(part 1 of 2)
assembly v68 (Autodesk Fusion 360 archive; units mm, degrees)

design "assembly" references "rear_port_bumber", "camera_w_shroud", "Wemos Battery Shield V3", "M5StickC", "mounting_adapter_v2", "Raspberry PI Zero W", "Rover_C_chassis_plate"
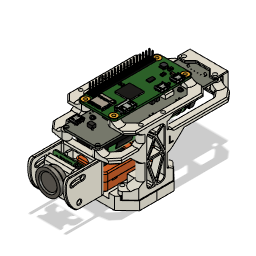
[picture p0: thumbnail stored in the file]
component_insert "Component Insert1"
component_insert "Component Insert2"
component_insert "Component Insert3"
component_insert "Component Insert4"
joint "Assemble1" alignAngle 180 alignOffsetX -5 alignOffsetY 0 alignOffsetZ 4
component_insert "Component Insert6"
joint "Assemble2" alignAngle 0 alignOffsetX 0 alignOffsetY 0 alignOffsetZ 0
joint "Assemble8" alignAngle -90 alignOffsetX 0 alignOffsetY 0 alignOffsetZ 0
position "Position1"
ground "Ground1"
position "Position2"
component_insert "Component Insert10"
joint "Assemble17" alignAngle -90 alignOffsetX 0 alignOffsetY 0 alignOffsetZ 0
joint "Assemble18" alignAngle 0 alignOffsetX 0 alignOffsetY 0 alignOffsetZ 0
component_insert "Component Insert11"
position "Position3"
joint "Assemble20" alignAngle 180 alignOffsetX 0 alignOffsetY 0 alignOffsetZ 0

design "Rover_C_chassis_plate"
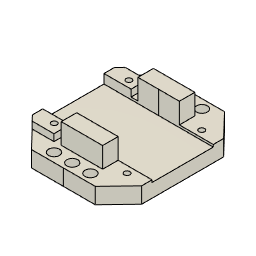
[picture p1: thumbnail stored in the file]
sketch "Sketch1" plane through (0, 0, 0) normal (0, 1, 0) x axis (1, 0, 0)
  line L1 (-14, 28.4) -> (0, 28.4)
  line L2 (-24, 18) -> (-14, 28.4)
  line L3 (-24, 0) -> (-24, 18)
  line L4 (-24, 0) -> (0, 0)
  line L5 (0, 28.4) -> (0, 0)
  line L6 (24, 18) -> (14, 28.4)
  line L7 (24, 0) -> (24, 18)
  line L8 (14, 28.4) -> (0, 28.4)
  line L9 (-24, -18) -> (-14, -28.4)
  line L10 (-14, -28.4) -> (0, -28.4)
  line L11 (14, -28.4) -> (0, -28.4)
  line L12 (24, -18) -> (14, -28.4)
  line L13 (24, 0) -> (24, -18)
  line L14 (-24, 0) -> (-24, -18)
  circle C1 centre (-8, 24.5) radius 2.4
  arc A1 centre (0, 24.5) radius 2.4 clockwise from (0, 22.1) to (0, 26.9)
  circle C2 centre (-16, 16.4) radius 1.25
  circle C3 centre (16, 16.4) radius 1.25
  circle C4 centre (8, 24.5) radius 2.4
  arc A2 centre (0, 24.5) radius 2.4 clockwise from (0, 26.9) to (0, 22.1)
  circle C5 centre (16, -16.4) radius 1.25
  circle C6 centre (8, -24.5) radius 2.4
  arc A3 centre (0, -24.5) radius 2.4 clockwise from (0, -22.1) to (0, -26.9)
  arc A4 centre (0, -24.5) radius 2.4 clockwise from (0, -26.9) to (0, -22.1)
  circle C7 centre (-8, -24.5) radius 2.4
  circle C8 centre (-16, -16.4) radius 1.25
  point P6 (-8, 24.5)
  point P7 (0, 24.5)
  point P1 (0, 0)
  point P11 (0, 0)
  point P12 (0, 0)
  point P8 (0, 22.1)
  point P9 (0, 26.9)
  point P13 (0, 26.9)
  point P2 (0, 28.4)
  point P22 (0, 28.4)
  point P3 (-14, 28.4)
  point P14 (14, 28.4)
  point P4 (-24, 18)
  point P15 (24, 18)
  point P5 (-24, 0)
  point P16 (24, 0)
  point P21 (0, 22.1)
  point P20 (0, 26.9)
  point P25 (0, -28.4)
  point P23 (-14, -28.4)
  point P24 (-24, -18)
  point P40 (-24, 0)
  point P37 (0, -22.1)
  point P36 (0, -26.9)
  point P27 (14, -28.4)
  point P28 (24, -18)
  point P29 (24, 0)
  point P34 (0, -26.9)
  point P33 (0, -22.1)
  point P26 (0, -28.4)
  point P10 (-16, 16.4)
  perpendicular L1 L3
  equal C1 A1
  horizontal P6 P7
  coincident P1 P11
  perpendicular L3 L4
  coincident P1 P12
  perpendicular L1 L5
  coincident P7 L5
  vertical L5
  coincident P8 L5
  coincident P9 L5
  coincident P9 P13
  symmetric P2 L5 P22
  symmetric P3 L5 P14
  symmetric P4 L5 P15
  symmetric P5 L5 P16
  symmetric C1 L5 C4
  symmetric P8 L5 P21
  symmetric P9 L5 P20
  symmetric A1 L5 A2
  symmetric C2 L5 C3
  symmetric P2 L4 P25
  symmetric P3 L4 P23
  symmetric P4 L4 P24
  symmetric P5 L4 P40
  symmetric C1 L4 C7
  symmetric P8 L4 P37
  symmetric P9 L4 P36
  symmetric A1 L4 A4
  symmetric C2 L4 C8
  symmetric L4 P14 P27
  symmetric L4 P15 P28
  symmetric L4 P16 P29
  symmetric L4 C3 C5
  symmetric L4 C4 C6
  symmetric L4 P20 P34
  symmetric L4 P21 P33
  symmetric L4 A2 A3
  symmetric L4 P22 P26
  dimension "d6" diameter C1 = 4.8
  dimension "d8" distance P6 P7 = 8
  dimension "d19" diameter C2 = 2.5
  dimension "d20" distance L3 P10 = 8
  dimension "d22" distance L1 P10 = 12
  dimension "d24" distance P2 P3 = 14
  dimension "d25" distance L3 L5 = 24
  dimension "d26" distance L1 L4 = 28.4
  dimension "d27" distance P4 P5 = 18
  dimension "d28" distance P2 P13 = 1.5
extrude "Extrude2" new body sketch "Sketch1" profile of L1 L2 L3 C1 A1 C2 L6 L7 C3 C4 A2 L8 L9 L10 L11 L12 L13 C5 C6 A3 A4 C7 C8 L14 along normal blind 7
sketch "Sketch2" plane through (0, 7, 0) normal (0, 1, 0) x axis (-1, 0, 0)
  line L1 (-14, 28.4) -> (0, 28.4)
  line L2 (-24, 18) -> (-14, 28.4)
  line L3 (-24, -18) -> (-24, 18)
  line L4 (-14, -28.4) -> (-24, -18)
  line L5 (0, -28.4) -> (-14, -28.4)
  line L6 (14, -28.4) -> (0, -28.4)
  line L7 (24, -18) -> (14, -28.4)
  line L8 (24, 18) -> (24, -18)
  line L9 (14, 28.4) -> (24, 18)
  line L10 (0, 28.4) -> (14, 28.4)
  line L11 (24, 0) -> (-24, 0)
  line L12 (0, -28.4) -> (0, 28.4)
  line L13 (-24, 13.45) -> (0, 13.45)
  line L14 (-9.1, 20.25) -> (-9.1, 13.45)
  line L15 (0, 20.25) -> (-9.1, 20.25)
  line L16 (9.1, 20.25) -> (9.1, 13.45)
  line L17 (0, 20.25) -> (9.1, 20.25)
  line L18 (24, 13.45) -> (0, 13.45)
  line L19 (0, -20.25) -> (-9.1, -20.25)
  line L20 (0, -20.25) -> (9.1, -20.25)
  line L21 (24, -13.45) -> (0, -13.45)
  line L22 (9.1, -20.25) -> (9.1, -13.45)
  line L23 (-9.1, -20.25) -> (-9.1, -13.45)
  line L24 (-24, -13.45) -> (0, -13.45)
  line L25 (12.1, 20.45) -> (12.1, 13.45)
  line L26 (21.6442, 20.45) -> (12.1, 20.45)
  line L27 (21.6442, -20.45) -> (12.1, -20.45)
  line L28 (12.1, -20.45) -> (12.1, -13.45)
  line L29 (-14, 28.4) -> (0, 28.4)
  line L30 (-24, 18) -> (-14, 28.4)
  line L31 (-24, -18) -> (-24, 18)
  line L32 (-14, -28.4) -> (-24, -18)
  line L33 (0, -28.4) -> (-14, -28.4)
  line L34 (14, -28.4) -> (0, -28.4)
  line L35 (24, -18) -> (14, -28.4)
  line L36 (24, 18) -> (24, -18)
  line L37 (14, 28.4) -> (24, 18)
  line L38 (0, 28.4) -> (14, 28.4)
  circle C1 centre (-8, 24.5) radius 2.4
  circle C2 centre (8, -24.5) radius 2.4
  circle C3 centre (-16, 16.4) radius 1.25
  circle C4 centre (0, -24.5) radius 2.4
  circle C5 centre (-8, -24.5) radius 2.4
  circle C6 centre (-16, -16.4) radius 1.25
  circle C7 centre (16, -16.4) radius 1.25
  circle C8 centre (0, 24.5) radius 2.4
  circle C9 centre (16, 16.4) radius 1.25
  circle C10 centre (8, 24.5) radius 2.4
  circle C11 centre (-16, 16.4) radius 1.25
  circle C12 centre (0, 24.5) radius 2.4
  circle C13 centre (8, -24.5) radius 2.4
  circle C14 centre (16, 16.4) radius 1.25
  circle C15 centre (-16, -16.4) radius 1.25
  circle C16 centre (0, -24.5) radius 2.4
  circle C17 centre (-8, 24.5) radius 2.4
  circle C18 centre (-8, -24.5) radius 2.4
  circle C19 centre (16, -16.4) radius 1.25
  circle C20 centre (8, 24.5) radius 2.4
  point P15 (-24, -18)
  point P23 (-24, 0)
  point P24 (24, 0)
  point P12 (0, 28.4)
  point P25 (0, 28.4)
  point P18 (0, -28.4)
  point P26 (0, -28.4)
  point P27 (0, 13.45)
  point P28 (-24, 13.45)
  point P29 (-9.1, 13.45)
  point P31 (0, 20.25)
  point P35 (0, 13.45)
  point P36 (24, 13.45)
  point P32 (9.1, 13.45)
  point P30 (-9.1, 20.25)
  point P33 (9.1, 20.25)
  point P34 (0, 20.25)
  point P45 (0, -13.45)
  point P46 (-24, -13.45)
  point P44 (-9.1, -13.45)
  point P37 (-9.1, -20.25)
  point P38 (0, -20.25)
  point P43 (9.1, -13.45)
  point P39 (9.1, -20.25)
  point P40 (0, -20.25)
  point P41 (0, -13.45)
  point P42 (24, -13.45)
  point P47 (12.1, 13.45)
  point P49 (21.6442, 20.45)
  point P52 (12.1, -13.45)
  point P48 (12.1, 20.45)
  point P50 (12.1, -20.45)
  point P51 (21.6442, -20.45)
  coincident P15 P23
  midpoint L8 P24
  coincident P12 P25
  coincident P18 P26
  coincident L12 P27
  coincident L3 P28
  perpendicular L3 L13
  coincident L13 P29
  perpendicular L13 L14
  coincident L12 P31
  perpendicular L12 L15
  symmetric L12 P27 P35
  symmetric L12 P28 P36
  symmetric L12 P29 P32
  symmetric L12 P30 P33
  symmetric L12 P31 P34
  symmetric L11 P27 P45
  symmetric L11 P28 P46
  symmetric L11 P29 P44
  symmetric L11 P30 P37
  symmetric L11 P31 P38
  symmetric L11 P32 P43
  symmetric L11 P33 P39
  symmetric L11 P34 P40
  symmetric L11 P35 P41
  symmetric L11 P36 P42
  coincident L18 P47
  perpendicular L18 L25
  coincident L9 P49
  perpendicular L25 L26
  symmetric L11 P47 P52
  symmetric L11 P48 P50
  symmetric L11 P49 P51
  dimension "d32" distance P29 P30 = 6.8
  dimension "d33" distance P30 P31 = 9.1
  dimension "d34" distance L11 L15 = 20.25
  dimension "d39" distance L16 L25 = 3
  dimension "d40" distance L18 L26 = 7
extrude "Extrude3" cut sketch "Sketch2" profile of L3 L8 L13 L18 L21 L24 against normal blind 1
extrude "Extrude4" add sketch "Sketch2" profile of C4 L13 L14 L15 L16 L17 L18 L19 L20 L21 L22 L23 L24 along normal blind 9
extrude "Extrude5" add sketch "Sketch2" profile of C7 C9 L7 L8 L9 L18 L21 L25 L26 L27 L28 along normal blind 3

design "Cam V2.1 v1"
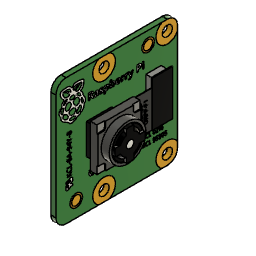
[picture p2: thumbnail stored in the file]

design "M5StickC"
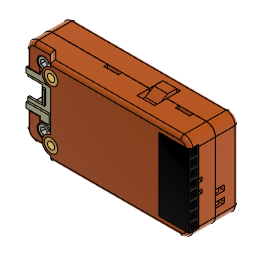
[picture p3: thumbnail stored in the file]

design "rear_port_bumber"
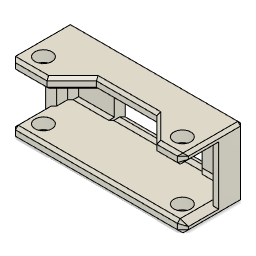
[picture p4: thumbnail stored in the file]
sketch "Sketch1" plane through (0, 0, 0) normal (0, 0, 1) x axis (1, 0, 0)
  line L1 (-5.75, 2.75) -> (8.25, 2.75)
  line L2 (-5.75, -3.75) -> (-5.75, 2.75)
  line L3 (8.25, -3.75) -> (-5.75, -3.75)
  line L4 (8.25, 2.75) -> (8.25, -3.75)
  line L5 (-15.75, 6.3) -> (15.75, 6.3)
  line L6 (-15.75, -6.3) -> (-15.75, 6.3)
  line L7 (15.75, -6.3) -> (-15.75, -6.3)
  line L8 (15.75, 6.3) -> (15.75, -6.3)
  line L9 (11.25, 4.3) -> (15.75, 4.3)
  line L10 (11.25, 6.3) -> (11.25, 4.3)
  line L11 (0, -6.3) -> (0, 6.3)
  line L12 (-11.25, 4.3) -> (-15.75, 4.3)
  line L13 (-11.25, 6.3) -> (-11.25, 4.3)
  line L14 (-15.75, 0) -> (15.75, 0)
  line L15 (11.25, -4.3) -> (15.75, -4.3)
  line L16 (11.25, -6.3) -> (11.25, -4.3)
  line L17 (-11.25, -6.3) -> (-11.25, -4.3)
  line L18 (-11.25, -4.3) -> (-15.75, -4.3)
  line L19 (1.25, -3.75) -> (1.25, 2.75)
  line L20 (-5.75, -0.5) -> (8.25, -0.5)
  line L21 (14.25, -4.3) -> (14.25, 4.3)
  line L22 (-14.25, -4.3) -> (-14.25, 4.3)
  point P10 (15.75, 4.3)
  point P12 (11.25, 6.3)
  point P13 (0, 6.3)
  point P14 (0, -6.3)
  point P15 (-15.75, 4.3)
  point P11 (11.25, 4.3)
  point P16 (-11.25, 4.3)
  point P17 (-11.25, 6.3)
  point P18 (15.75, 0)
  point P19 (-15.75, 0)
  point P20 (15.75, -4.3)
  point P21 (11.25, -4.3)
  point P22 (11.25, -6.3)
  point P25 (-15.75, -4.3)
  point P23 (-11.25, -4.3)
  point P24 (-11.25, -6.3)
  point P1 (0, 0)
  point P26 (1.25, 2.75)
  point P27 (1.25, -3.75)
  point P28 (8.25, -0.5)
  point P29 (-5.75, -0.5)
  point P30 (14.25, 4.3)
  point P31 (14.25, -4.3)
  point P32 (-14.25, 4.3)
  point P33 (-14.25, -4.3)
  point P2 (8.25, 2.75)
  point P3 (-5.75, 2.75)
  point P5 (8.25, -3.75)
  horizontal L1
  vertical L2
  horizontal L3
  vertical L4
  horizontal L5
  vertical L6
  horizontal L7
  vertical L8
  coincident L8 P10
  perpendicular L8 L9
  coincident L5 P12
  perpendicular L9 L10
  midpoint L5 P13
  midpoint L7 P14
  symmetric P10 L11 P15
  symmetric P11 L11 P16
  symmetric P12 L11 P17
  midpoint L8 P18
  coincident L6 P19
  perpendicular L6 L14
  symmetric P10 L14 P20
  symmetric P11 L14 P21
  symmetric P12 L14 P22
  symmetric P15 L14 P25
  symmetric P16 L14 P23
  symmetric P17 L14 P24
  midpoint P1 L11
  midpoint L1 P26
  midpoint L3 P27
  midpoint L4 P28
  midpoint L2 P29
  coincident L9 P30
  coincident L15 P31
  perpendicular L15 L21
  symmetric L11 P30 P32
  symmetric L11 P31 P33
  dimension "d1" distance P2 P3 = 14
  dimension "d11" distance P2 P5 = 6.5
  dimension "d18" distance P11 P12 = 2
  dimension "d19" distance P10 P11 = 4.5
  dimension "d29" distance L7 L14 = 6.3
  dimension "d30" distance P1 L8 = 15.75
  dimension "d33" distance L11 L19 = 1.25
  dimension "d34" distance L14 L20 = 0.5
  dimension "d57" distance L8 L21 = 1.5
extrude "Extrude1" new body sketch "Sketch1" profile of L1 L2 L3 L4 L5 L6 L7 L8 along normal blind 1.5
extrude "Extrude2" sketch "Sketch1" profile of L5 L6 L7 L8 L9 L10 L12 L13 L15 L16 L17 L18 blind 10
extrude "Extrude4" add of existing geometry to an object
extrude "Extrude5" add of existing geometry to an object
extrude "Extrude8" sketch "Sketch1" profile of L6 L8 L9 L12 L15 L18 L21 L22 blind 4
sketch "Sketch4" plane through (0, 6.3, 0) normal (0, 1, 0) x axis (-1, 0, 0)
  line L1 (15.75, 0) -> (-15.75, 0)
  line L2 (15.75, 11.5) -> (15.75, 0)
  line L3 (-15.75, 11.5) -> (15.75, 11.5)
  line L4 (-15.75, 0) -> (-15.75, 11.5)
  line L5 (-8.75, 7) -> (-8.75, 11.5)
  line L6 (6.75, 7) -> (-8.75, 7)
  line L7 (6.75, 11.5) -> (6.75, 7)
  point P6 (-8.75, 11.5)
  point P9 (6.75, 11.5)
  point P7 (-8.75, 7)
  point P8 (6.75, 7)
  coincident L3 P6
  perpendicular L3 L5
  perpendicular L5 L6
  coincident L3 P9
  perpendicular L3 L7
  dimension "d39" distance P7 P8 = 15.5
  dimension "d40" distance P6 P7 = 4.5
  dimension "d41" distance L4 L5 = 7
extrude "Extrude6" cut sketch "Sketch4" profile of L3 L5 L6 L7 to an object
chamfer "Chamfer1" distance 1 distance 2.25 distance 1 distance 0.5
sketch "Sketch5" plane through (0, 6.3, 0) normal (0, 1, 0) x axis (-1, 0, 0)
  line L1 (-6.5, 7) -> (4.5, 7)
  line L2 (-15.25, 11) -> (-10.5, 11)
  line L3 (-15.25, 1) -> (-15.25, 11)
  line L4 (15.25, 1) -> (-15.25, 1)
  line L5 (15.25, 11) -> (15.25, 1)
  line L6 (0, 11) -> (0, 0)
  line L7 (-15.75, 1) -> (-15.75, 10.5)
  line L8 (-10.5, 11) -> (-6.5, 7)
  line L9 (8.5, 11) -> (15.25, 11)
  line L10 (4.5, 7) -> (8.5, 11)
  line L11 (-14.75, 11.5) -> (-11, 11.5)
  line L12 (9, 11.5) -> (14.75, 11.5)
  circle C1 centre (-12.65, 8.5) radius 1.55
  circle C2 centre (12.65, 8.5) radius 1.55
  point P1 (0, 0)
  point P10 (0, 0)
  point P4 (-10.5, 11)
  point P11 (0, 11)
  point P9 (-12.65, 8.5)
  coincident P1 P10
  perpendicular L4 L6
  horizontal P4 P11
  symmetric C1 L6 C2
  dimension "d50" diameter C1 = 3.1
  dimension "d56" distance P9 L6 = 12.65 (= "( 25.3 / 2 ) * 1 mm")
extrude "Extrude7" cut sketch "Sketch5" profile of C1 C2 to an object
chamfer "Chamfer2" distance 0.5
sketch "Sketch6" plane through (0, 0, 0) normal (0, 0, -1) x axis (-1, 0, 0)
  line L1 (-14.75, -5.3) -> (-14.75, 5.3)
  line L2 (14.75, -5.3) -> (-14.75, -5.3)
  line L3 (14.75, 5.3) -> (14.75, -5.3)
  line L4 (-14.75, 5.3) -> (14.75, 5.3)
  line L5 (-8.75, 3.25) -> (-8.75, -4.25)
  line L6 (6.25, 3.25) -> (-8.75, 3.25)
  line L7 (6.25, -4.25) -> (6.25, 3.25)
  line L8 (-8.75, -4.25) -> (6.25, -4.25)
  curve K1
  curve K2
  curve K3
  curve K4
  coincident L7
  coincident L4
  coincident L3
  vertical K2
  coincident L2
  dimension "d62" Text1-Height = 4.8
extrude "Extrude9" cut sketch "Sketch6" against normal blind 0.5
named bodies: "bumper"

design "adjustable_camera_shroud_mount_w_lens"
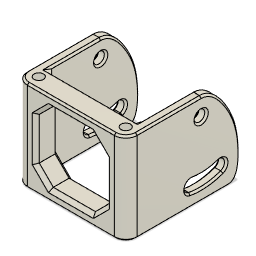
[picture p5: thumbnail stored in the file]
sketch "Sketch1" plane through (0, 0, 0) normal (0, 1, 0) x axis (1, 0, 0)
  line L1 (0, 3.25) -> (0, -3.25)
  line L2 (12.4, 0) -> (-12.4, 0)
  line L3 (12.4, 3.25) -> (-12.4, 3.25)
  line L4 (12.4, -3.25) -> (-12.4, -3.25)
  line L5 (-8.15, -3.25) -> (-8.15, 3.25)
  line L6 (8.15, -3.25) -> (8.15, 3.25)
  line L7 (-15.65, 40) -> (-15.65, 0)
  line L8 (-13, 40) -> (-15.65, 40)
  line L9 (15.65, 40) -> (15.65, 0)
  line L10 (13, 40) -> (15.65, 40)
  line L11 (-15.65, 3.25) -> (-12.4, 3.25)
  line L12 (15.65, 3.25) -> (12.4, 3.25)
  line L13 (-13, 3.25) -> (-13, 40)
  line L14 (13, 3.25) -> (13, 40)
  circle C1 centre (-12.4, 0) radius 1.35
  circle C2 centre (12.4, 0) radius 1.35
  arc A1 centre (-12.4, 0) radius 3.25 clockwise from (-12.4, -3.25) to (-12.4, 3.25)
  arc A2 centre (12.4, 0) radius 3.25 clockwise from (12.4, 3.25) to (12.4, -3.25)
  arc A3 centre (-12.4, 0) radius 3.25 clockwise from (-12.4, 3.25) to (-12.4, -3.25)
  point P1 (0, 0)
  point P2 (-12.4, 0)
  point P5 (12.4, 0)
  point P6 (-12.4, 0)
  point P7 (12.4, 0)
  point P8 (0, 0)
  point P9 (-12.4, 3.25)
  point P11 (-12.4, -3.25)
  point P12 (12.4, -3.25)
  point P10 (12.4, 3.25)
  point P13 (-12.4, 0)
  point P4 (0, 3.25)
  point P15 (-11.05, 0)
  point P16 (-15.65, 0)
  point P17 (-13.75, 0)
  point P19 (-9.15, 0)
  point P20 (-8.15, 3.25)
  point P21 (-8.15, -3.25)
  point P22 (8.15, 3.25)
  point P23 (8.15, -3.25)
  point P24 (-15.65, 0)
  point P27 (15.65, 0)
  point P25 (-15.65, 40)
  point P28 (15.65, 40)
  point P26 (-13, 40)
  point P29 (13, 40)
  point P30 (-15.65, 3.25)
  point P31 (15.65, 3.25)
  point P32 (-13, 3.25)
  point P33 (13, 3.25)
  vertical L1
  midpoint P1 L1
  horizontal P2 P5
  equal C1 C2
  coincident P2 P6
  coincident P5 P7
  midpoint L2 P8
  coincident P1 P8
  perpendicular L1 L3
  vertical P2 P9
  vertical P2 P11
  vertical P5 P12
  vertical P5 P10
  tangent L3 A1
  tangent L3 A2
  coincident P2 P13
  coincident P4 L3
  coincident L2 P15
  coincident C1 P15
  midpoint A1 P16
  coincident C1 P17
  tangent L4 A3
  midpoint A3 P19
  coincident L3 P20
  coincident L4 P21
  perpendicular L4 L5
  symmetric L1 P20 P22
  symmetric L1 P21 P23
  coincident P16 P24
  tangent A1 L7
  vertical L7
  perpendicular L7 L8
  symmetric L1 P24 P27
  symmetric L1 P25 P28
  symmetric L1 P26 P29
  coincident L7 P30
  tangent A1 L11
  coincident L9 P31
  tangent A2 L12
  coincident L3 P32
  perpendicular L3 L13
  coincident L3 P33
  perpendicular L3 L14
  dimension "d2" diameter C1 = 2.7
  dimension "d3" distance P2 P5 = 24.8 (= "25.3 mm - 0.5 mm")
  dimension "d4" distance L3 L4 = 6.5
  dimension "d15" distance P19 L5 = 1
  dimension "d19" distance P16 L8 = 40
  dimension "d24" distance L13 L14 = 26
extrude "Extrude1" new body sketch "Sketch1" profile of C1 C2 L3 L4 A1 A2 A3 L5 L6 along normal blind 26
extrude "Extrude3" cut sketch "Sketch1" profile of C1 C2 along normal blind 6
extrude "Extrude4" add sketch "Sketch1" profile of L3 L4 L5 L6 against normal blind 4
extrude "Extrude5" add sketch "Sketch1" profile of A1 A2 L7 L8 L9 L10 L11 L12 L13 L14 to an object
extrude "Extrude8" sketch "Sketch1" profile of C1 C2 blind -6
sketch "Sketch2" plane through (15.65, 0, 0) normal (1, 0, 0) x axis (0, 0, -1)
  line L1 (0, 26) -> (40, 26)
  line L2 (0, 0) -> (0, 26)
  line L3 (40, 0) -> (0, 0)
  line L4 (40, 26) -> (40, 0)
  line L5 (18.25, 21) -> (18.25, 5)
  line L6 (3.25, 26) -> (3.25, 0)
  line L7 (3.25, 13) -> (40, 13)
  line L8 (18.25, 21) -> (24.3038, 4.3674)
  line L9 (18.25, 21) -> (15.1764, 3.5689)
  line L10 (25.8934, 0) -> (24.3038, 4.3674)
  curve K1 (18.25, 26) -> (25.8934, 0)
  curve K2 (28.3934, 0) -> (23.3934, 0)
  curve K3 (15.75, 26) -> (20.75, 26)
  circle C1 centre (18.25, 21) radius 1.55
  circle C2 centre (18.25, 5) radius 1.55
  arc A1 centre (18.25, 21) radius 17.7 clockwise from (24.3038, 4.3674) to (15.1764, 3.5689)
  arc A2 centre (18.25, 21) radius 14.3 clockwise from (23.1409, 7.5624) to (15.7668, 6.9172)
  arc A3 centre (23.7223, 5.9649) radius 1.7 clockwise from (23.1409, 7.5624) to (24.3038, 4.3674)
  arc A4 centre (15.4716, 5.2431) radius 1.7 clockwise from (15.1764, 3.5689) to (15.7668, 6.9172)
  point P7 (18.25, 21)
  point P8 (18.25, 21)
  point P6 (18.25, 5)
  point P9 (18.25, 5)
  point P10 (3.25, 0)
  point P11 (3.25, 26)
  point P14 (18.25, 13)
  point P15 (18.25, 21)
  point P18 (18.25, 21)
  point P19 (18.25, 21)
  point P21 (15.7668, 6.9172)
  point P20 (18.25, 21)
  point P22 (23.1409, 7.5624)
  point P25 (25.8934, 0)
  point P13 (3.25, 13)
  point P12 (40, 13)
  point P28 (18.25, 26)
  point P30 (28.3934, 0)
  point P31 (20.75, 26)
  point P1 (0, 0)
  point P16 (15.1764, 3.5689)
  point P26 (29.25, 8)
  point P27 (26.25, 19)
  point P32 (15.75, 26)
  vertical L5
  coincident P7 P8
  coincident P6 P9
  equal C1 C2
  coincident L3 P10
  coincident L1 P11
  perpendicular L1 L6
  midpoint L5 P14
  coincident L7 P14
  coincident P7 P15
  coincident P8 P18
  coincident P15 P19
  coincident L9 P21
  coincident P8 P20
  coincident L8 P22
  tangent A2 A3
  tangent A1 A4
  coincident L3 P25
  coincident L3 P25
  parallel L8 L10
  horizontal L7
  coincident L6 P13
  coincident L4 P12
  coincident L3 P25
  coincident L1 P28
  midpoint P25 K2
  coincident L3 P30
  midpoint P28 K3
  coincident L1 P31
  vertical P15 P28
  equal K2 K3
  dimension "d25" diameter C1 = 3.1
  dimension "d26" distance P6 P7 = 16
  dimension "d27" distance P1 L6 = 3.25
  dimension "d28" distance L5 L6 = 15
  dimension "d30" angle L8 L9 = 30
  dimension "d31" angle L5 L9 = 10
  dimension "d32" distance P16 P21 = 3.4
  dimension "d33" distance P15 P21 = 14.3
  dimension "d72" distance L3 L7 = 13
  dimension "d81" distance L7 P26 = 5
  dimension "d82" distance L7 P27 = 6
  dimension "d83" distance P26 P27 = 3
  dimension "d84" distance L5 P27 = 8
  dimension "d85" distance P31 P32 = 5
extrude "Extrude6" cut sketch "Sketch2" profile of L1 L3 L4 C1 A1 A2 A3 A4 to an object
sketch "Sketch3" plane through (0, 0, -3.25) normal (0, 0, -1) x axis (-1, 0, 0)
  line L1 (13, 0) -> (-13, 0)
  line L2 (13, 26) -> (13, 0)
  line L3 (-13, 26) -> (13, 26)
  line L4 (-13, 0) -> (-13, 26)
  line L5 (0, 26) -> (0, 0)
  line L6 (-10, 3) -> (10, 3)
  line L7 (-10, 23) -> (-10, 3)
  line L8 (10, 23) -> (-10, 23)
  line L9 (10, 3) -> (10, 23)
  line L10 (-10, 13) -> (10, 13)
  point P1 (0, 0)
  point P6 (0, 0)
  point P7 (0, 26)
  point P12 (0, 3)
  point P13 (0, 23)
  point P14 (-10, 13)
  point P15 (10, 13)
  point P16 (10, 13)
  point P17 (-10, 13)
  coincident P1 P6
  midpoint L3 P7
  horizontal L6
  vertical L7
  horizontal L8
  vertical L9
  midpoint L6 P12
  midpoint L8 P13
  midpoint L7 P14
  midpoint L9 P15
  coincident P15 P16
  coincident P14 P17
  midpoint L5 L10
  dimension "d45" distance P12 P13 = 20
  dimension "d46" distance P14 P15 = 20
extrude "Extrude7" cut sketch "Sketch3" profile of L6 L7 L8 L9 to an object
chamfer "Chamfer1" distance 4 distance 1 distance 0.5
chamfer "Chamfer2" distance 1
named bodies: "cam_bracket"

design "camera_w_shroud" references "macro_0.67xwideangle_lens", "lens_mount_adapter_maglock", "Cam V2.1 v1", "adjustable_camera_shroud_mount_w_lens", "camera_mounting_shroud", "fisheye_lens_180degFoV"
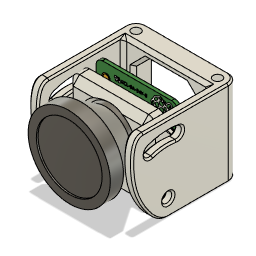
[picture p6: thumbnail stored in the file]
component_insert "Component Insert1"
component_insert "Component Insert2"
joint "Assemble1" alignAngle 180 alignOffsetX 0 alignOffsetY 0 alignOffsetZ 0
component_insert "Component Insert4"
component_insert "Component Insert5"
joint "Assemble2" alignAngle 180 alignOffsetX 0 alignOffsetY 0 alignOffsetZ 0
joint "Assemble3" alignAngle 0 alignOffsetX 0 alignOffsetY 0 alignOffsetZ 0
component_insert "Component Insert6"
joint "Assemble4" alignAngle 0 alignOffsetX 0 alignOffsetY 0 alignOffsetZ 0.5 RotateMinimum -20 RotateMaximum 10
position "Position1"
ground "Ground1"
component_insert "Component Insert7"
joint "Assemble5" alignAngle 0 alignOffsetX 0 alignOffsetY 0 alignOffsetZ 0

design "mounting_adapter_v2"
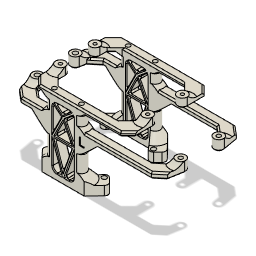
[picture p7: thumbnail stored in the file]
sketch "Sketch1" plane through (0, 0, 0) normal (0, 1, 0) x axis (1, 0, 0)
  line L1 (0, 28.4) -> (0, 0)
  line L2 (14, 28.4) -> (0, 28.4)
  line L3 (-14, 28.4) -> (0, 28.4)
  line L4 (-14, -28.4) -> (0, -28.4)
  line L5 (-24, 0) -> (-24, 18)
  line L6 (14, -28.4) -> (0, -28.4)
  line L7 (24, 18) -> (14, 28.4)
  line L8 (-24, -18) -> (-14, -28.4)
  line L9 (24, 0) -> (24, -18)
  line L10 (24, -18) -> (14, -28.4)
  line L11 (24, 0) -> (24, 18)
  line L12 (-24, 0) -> (-24, -18)
  line L13 (-24, 0) -> (0, 0)
  line L14 (-24, 18) -> (-14, 28.4)
  line L15 (24, 13.45) -> (-24, 13.45)
  line L16 (-9.1, 20.25) -> (-9.1, 13.45)
  line L17 (9.1, 20.25) -> (-9.1, 20.25)
  line L18 (9.1, 13.45) -> (9.1, 20.25)
  line L19 (24, -13.45) -> (-24, -13.45)
  line L20 (-9.1, -20.25) -> (-9.1, -13.45)
  line L21 (9.1, -20.25) -> (-9.1, -20.25)
  line L22 (9.1, -13.45) -> (9.1, -20.25)
  line L23 (-16, 28.4) -> (-16, 13.9)
  line L24 (0, 21.25) -> (-9, 21.25)
  line L25 (-9, 21.25) -> (-14.0357, 14.8536)
  line L26 (-20.5438, 17.4082) -> (-17.7678, 14.6322)
  line L27 (-14, 27.75) -> (-20.5781, 20.9088)
  line L28 (0, 27.75) -> (-14, 27.75)
  line L29 (22.4208, -18.9924) -> (18.4142, -14.9858)
  line L30 (9.3216, -21.25) -> (15.5858, -14.9858)
  line L31 (14, -27.75) -> (22.4208, -18.9924)
  line L32 (0, -27.75) -> (14, -27.75)
  line L33 (0, -21.25) -> (9.3216, -21.25)
  line L34 (0, -21.25) -> (-9, -21.25)
  line L35 (0, -27.75) -> (-14, -27.75)
  line L36 (-14, -27.75) -> (-22.2893, -19.1295)
  line L37 (-9, -21.25) -> (-14.0357, -14.8536)
  line L38 (-22.2893, -19.1295) -> (-17.7678, -14.6322)
  line L39 (0, 21.25) -> (9, 21.25)
  line L40 (9, 21.25) -> (14.0357, 14.8536)
  line L41 (20.5438, 17.4082) -> (17.7678, 14.6322)
  line L42 (14, 27.75) -> (20.5781, 20.9088)
  line L43 (0, 27.75) -> (14, 27.75)
  line L44 (-9.5511, 20.55) -> (-20.9231, 20.55)
  arc A1 centre (0, 24.5) radius 2.4 clockwise from (0, 22.1) to (0, 26.9)
  circle C1 centre (8, 24.5) radius 2.4
  circle C2 centre (16, -16.4) radius 1.55
  arc A2 centre (0, 24.5) radius 2.4 clockwise from (0, 26.9) to (0, 22.1)
  circle C3 centre (-16, 16.4) radius 1.55
  circle C4 centre (8, -24.5) radius 2.4
  circle C5 centre (-8, -24.5) radius 2.4
  arc A3 centre (0, -24.5) radius 2.4 clockwise from (0, -22.1) to (0, -26.9)
  circle C6 centre (-16, -16.4) radius 1.55
  circle C7 centre (-8, 24.5) radius 2.4
  arc A4 centre (0, -24.5) radius 2.4 clockwise from (0, -26.9) to (0, -22.1)
  circle C8 centre (16, 16.4) radius 1.55
  circle C9 centre (-16, 16.4) radius 2.5
  circle C10 centre (17, -16.4) radius 2
  circle C11 centre (-16, -16.4) radius 2.5
  arc A5 centre (-18.776, 19.176) radius 2.5 clockwise from (-20.5438, 17.4082) to (-20.5781, 20.9088)
  circle C12 centre (16, 16.4) radius 2.5
  arc A6 centre (18.776, 19.176) radius 2.5 clockwise from (20.5781, 20.9088) to (20.5438, 17.4082)
  arc A7 centre (-9, 24.5) radius 3.25 clockwise from (-9, 21.25) to (-9, 27.75)
  arc A8 centre (9, 24.5) radius 3.25 clockwise from (9, 27.75) to (9, 21.25)
  point P9 (0, 24.5)
  point P30 (-8, 24.5)
  point P16 (0, 0)
  point P26 (0, 0)
  point P27 (0, 0)
  point P37 (0, 22.1)
  point P13 (0, 26.9)
  point P28 (0, 26.9)
  point P18 (0, 28.4)
  point P39 (0, 28.4)
  point P2 (14, 28.4)
  point P22 (-14, 28.4)
  point P23 (24, 18)
  point P41 (-24, 18)
  point P10 (24, 0)
  point P17 (-24, 0)
  point P32 (0, 22.1)
  point P34 (0, 26.9)
  point P40 (0, -28.4)
  point P15 (-14, -28.4)
  point P25 (-24, -18)
  point P6 (-24, 0)
  point P7 (0, -22.1)
  point P3 (0, -26.9)
  point P31 (14, -28.4)
  point P24 (24, -18)
  point P19 (24, 0)
  point P11 (0, -26.9)
  point P14 (0, -22.1)
  point P29 (0, -28.4)
  point P1 (0, 0)
  point P42 (-24, 13.45)
  point P43 (24, 13.45)
  point P44 (-9.1, 13.45)
  point P47 (9.1, 13.45)
  point P48 (0, 20.25)
  point P49 (-24, -13.45)
  point P50 (24, -13.45)
  point P51 (-9.1, -13.45)
  point P45 (-9.1, 20.25)
  point P52 (-9.1, -20.25)
  point P46 (9.1, 20.25)
  point P53 (9.1, -20.25)
  point P54 (9.1, -13.45)
  point P56 (-16, 28.4)
  point P8 (-16, 16.4)
  point P58 (0, 21.25)
  point P55 (-16, 13.9)
  point P60 (-14.0357, 14.8536)
  point P61 (-17.7678, 14.6322)
  point P63 (0, 27.75)
  point P62 (-14, 27.75)
  point P57 (-9, 21.25)
  point P72 (-9, -21.25)
  point P73 (0, -21.25)
  point P77 (-14.0357, -14.8536)
  point P79 (-17.7678, -14.6322)
  point P74 (-14, -27.75)
  point P75 (0, -27.75)
  point P83 (9, 21.25)
  point P84 (0, 21.25)
  point P85 (14.0357, 14.8536)
  point P87 (17.7678, 14.6322)
  point P91 (14, 27.75)
  point P92 (0, 27.75)
  point P80 (-20.5438, 17.4082)
  point P88 (20.5438, 17.4082)
  point P81 (-20.5781, 20.9088)
  point P90 (20.5781, 20.9088)
  point P93 (-9, 27.75)
  point P94 (-9, 24.5)
  point P97 (9, 21.25)
  point P96 (9, 27.75)
  point P98 (-20.9231, 20.55)
  point P99 (-9.5511, 20.55)
  perpendicular L3 L5
  equal A1 C7
  horizontal P9 P30
  coincident P16 P26
  perpendicular L5 L13
  coincident P16 P27
  perpendicular L1 L3
  coincident P9 L1
  vertical L1
  coincident P37 L1
  coincident P13 L1
  coincident P13 P28
  symmetric P18 P39 L1
  symmetric P2 P22 L1
  symmetric P23 P41 L1
  symmetric P10 P17 L1
  symmetric L1 C1 C7
  symmetric P32 P37 L1
  symmetric P13 P34 L1
  symmetric L1 A1 A2
  symmetric L1 C3 C8
  symmetric P18 P40 L13
  symmetric P15 P22 L13
  symmetric P25 P41 L13
  symmetric P6 P17 L13
  symmetric C5 C7 L13
  symmetric P7 P37 L13
  symmetric P3 P13 L13
  symmetric A1 A4 L13
  symmetric C3 C6 L13
  symmetric P2 P31 L13
  symmetric P23 P24 L13
  symmetric P10 P19 L13
  symmetric C2 C8 L13
  symmetric C1 C4 L13
  symmetric P11 P34 L13
  symmetric P14 P32 L13
  symmetric A2 A3 L13
  symmetric P29 P39 L13
  coincident P1 P16
  coincident L5 P42
  coincident L11 P43
  perpendicular L11 L15
  coincident L15 P44
  perpendicular L15 L16
  perpendicular L16 L17
  coincident L15 P47
  perpendicular L15 L18
  coincident L1 P48
  midpoint L17 P48
  symmetric L13 P42 P49
  symmetric L13 P43 P50
  symmetric L13 P44 P51
  symmetric L13 P45 P52
  symmetric L13 P46 P53
  symmetric L13 P47 P54
  horizontal P22 P56
  coincident P8 L23
  coincident L1 P58
  perpendicular L1 L24
  concentric C3 C9
  coincident P55 C9
  coincident C9 P60
  vertical L23
  coincident C9 P61
  tangent C9 L26
  coincident L1 P63
  perpendicular L1 L28
  tangent C9 L25
  parallel L14 L27
  vertical P22 P62
  symmetric L13 P57 P72
  symmetric L13 P58 P73
  symmetric L13 C9 C11
  symmetric L13 P60 P77
  symmetric L13 P61 P79
  symmetric L13 P62 P74
  symmetric L13 P63 P75
  tangent L26 A5
  tangent L27 A5
  symmetric L1 P57 P83
  symmetric L1 P58 P84
  symmetric L1 C9 C12
  symmetric L1 P60 P85
  symmetric L1 P61 P87
  symmetric L1 P62 P91
  symmetric L1 P63 P92
  symmetric L1 P80 P88
  symmetric L1 P81 P90
  symmetric L1 A5 A6
  coincident L28 P93
  vertical P57 P94
  vertical P93 P94
  symmetric L1 P57 P97
  symmetric L1 P93 P96
  symmetric L1 A7 A8
  coincident L27 P98
  coincident L25 P99
  horizontal L44
  dimension "d6" diameter C7 = 4.8
  dimension "d8" distance P9 P30 = 8
  dimension "d19" diameter C3 = 3.1
  dimension "d20" distance P8 L5 = 8
  dimension "d22" distance P8 L3 = 12
  dimension "d24" distance P18 P22 = 14
  dimension "d25" distance L1 L5 = 24
  dimension "d26" distance L3 L13 = 28.4
  dimension "d27" distance P17 P41 = 18
  dimension "d28" distance P18 P28 = 1.5
  dimension "d13" distance P45 P46 = 18.2 (= "( 9.1 * 2 ) * 1 mm")
  dimension "d14" distance L15 L17 = 6.8
  dimension "d16" distance L13 P48 = 20.25
  dimension "d32" distance P48 L24 = 1
  dimension "d33" diameter C9 = 5
  dimension "d36" distance P34 P63 = 0.85
  dimension "d37" angle L23 L26 = 45
  dimension "d41" radius A5 = 2.5
  dimension "d51" distance P57 P58 = 9
  dimension "d102" distance L15 L44 = 7.1
extrude "Extrude1" new body sketch "Sketch1" profile of C3 C8 L24 C9 L25 L26 L27 L28 A5 L39 L40 C12 L41 A6 L42 L43 along normal blind 6
extrude "Extrude2" sketch "Sketch1" profile of A1 C1 A2 C7 L24 L28 L39 L43 A7 A8 blind 43
extrude "Extrude3" cut sketch "Sketch1" profile of C3 C9 L25 L26 L27 A5 L44 along normal blind 3
sketch "Sketch5" plane through (0, 49, 0) normal (0, 1, 0) x axis (-1, 0, 0)
  line L1 (9, -27.75) -> (-9, -27.75)
  line L2 (-9, -21.25) -> (9, -21.25)
  line L3 (-63.05, -14.65) -> (32.25, -14.65)
  line L4 (-65.05, 12.65) -> (-65.05, -12.65)
  line L5 (32.25, 14.65) -> (-63.05, 14.65)
  line L6 (34.25, -12.65) -> (34.25, 12.65)
  line L7 (-15.4, 14.65) -> (-15.4, -14.65)
  line L8 (-65.05, 0) -> (34.25, 0)
  line L9 (27.4335, -21.25) -> (9, -21.25)
  line L10 (29.0494, -12.0856) -> (27.4335, -21.25)
  line L11 (32.8876, -27.75) -> (9, -27.75)
  line L12 (35.4506, -13.2144) -> (32.8876, -27.75)
  line L13 (-58.2335, -21.25) -> (-9, -21.25)
  line L14 (-59.8494, -12.0856) -> (-58.2335, -21.25)
  line L15 (-63.6876, -27.75) -> (-9, -27.75)
  line L16 (-66.2506, -13.2144) -> (-63.6876, -27.75)
  line L17 (34.3, -12.65) -> (34.3, -10.1281)
  line L18 (-65.1, -10.1281) -> (-65.1, -12.65)
  line L19 (28.5884, -14.7) -> (32.25, -14.7)
  line L20 (-63.05, -14.7) -> (-59.3884, -14.7)
  arc A1 centre (9, -24.5) radius 3.25 clockwise from (9, -21.25) to (9, -27.75)
  arc A2 centre (-9, -24.5) radius 3.25 clockwise from (-9, -27.75) to (-9, -21.25)
  circle C1 centre (32.25, -12.65) radius 1.55
  circle C2 centre (-63.05, -12.65) radius 1.35
  circle C3 centre (32.25, -12.65) radius 3.25
  circle C4 centre (-63.05, -12.65) radius 3.25
  circle C5 centre (32.25, -12.65) radius 1.5
  arc A3 centre (32.25, -12.65) radius 2 clockwise from (34.25, -12.65) to (32.25, -14.65)
  arc A4 centre (32.25, 12.65) radius 2 clockwise from (32.25, 14.65) to (34.25, 12.65)
  arc A5 centre (-63.05, -12.65) radius 2 clockwise from (-63.05, -14.65) to (-65.05, -12.65)
  arc A6 centre (-63.05, 12.65) radius 2 clockwise from (-65.05, 12.65) to (-63.05, 14.65)
  circle C6 centre (32.25, 12.65) radius 1.5
  circle C7 centre (-63.05, -12.65) radius 1.5
  circle C8 centre (-63.05, 12.65) radius 1.5
  arc A7 centre (32.25, -12.65) radius 2.05 clockwise from (34.3, -12.65) to (32.25, -14.7)
  arc A8 centre (-63.05, -12.65) radius 2.05 clockwise from (-63.05, -14.7) to (-65.1, -12.65)
  point P8 (32.25, -12.65)
  point P9 (-63.05, -12.65)
  point P10 (12.25, -24.5)
  point P11 (-12.25, -24.5)
  point P15 (-15.4, -14.65)
  point P14 (32.25, -12.65)
  point P19 (32.25, -12.65)
  point P16 (-15.4, 14.65)
  point P29 (34.25, 0)
  point P30 (-65.05, 0)
  point P12 (32.25, -12.65)
  point P13 (-63.05, -12.65)
  point P25 (-63.05, -12.65)
  point P4 (9, -21.25)
  point P34 (9, -21.25)
  point P36 (29.0494, -12.0856)
  point P3 (9, -27.75)
  point P37 (9, -27.75)
  point P39 (35.4506, -13.2144)
  point P6 (-9, -21.25)
  point P40 (-9, -21.25)
  point P42 (-59.8494, -12.0856)
  point P2 (-9, -27.75)
  point P43 (-9, -27.75)
  point P45 (-66.2506, -13.2144)
  point P52 (34.3, -10.1281)
  point P53 (28.5884, -14.7)
  point P54 (-59.3884, -14.7)
  point P55 (-65.1, -10.1281)
  horizontal P8 P9
  midpoint A1 P10
  midpoint A2 P11
  concentric C1 C3
  concentric C2 C4
  equal C3 C4
  horizontal L3
  vertical L4
  horizontal L5
  vertical L6
  coincident L3 P15
  tangent L3 A3
  tangent L6 A3
  coincident P14 P19
  coincident L5 P16
  tangent L5 A4
  tangent L6 A4
  tangent L3 A5
  tangent L4 A5
  tangent L4 A6
  tangent L5 A6
  equal A5 A6
  midpoint L3 P15
  coincident L6 P29
  coincident L4 P30
  perpendicular L4 L8
  midpoint L6 P29
  symmetric C5 L8 C6
  symmetric C5 L7 C7
  symmetric L7 C6 C8
  vertical L7
  coincident P12 P14
  coincident P13 P25
  coincident P4 P34
  tangent A1 L9
  coincident C3 P36
  coincident P3 P37
  tangent A1 L11
  coincident C3 P39
  tangent C3 L12
  tangent C3 L10
  parallel L10 L12
  coincident P6 P40
  tangent A2 L13
  coincident C4 P42
  tangent C4 L14
  coincident P2 P43
  tangent A2 L15
  coincident C4 P45
  tangent C4 L16
  parallel L14 L16
  concentric A3 A7
  concentric A5 A8
  tangent A8 L19
  tangent L17 A7
  tangent A7 L19
  tangent A8 L18
  coincident C3 P52
  coincident L10 P53
  coincident L14 P54
  collinear L19 L20
  coincident C4 P55
  dimension "d53" diameter C1 = 3.1
  dimension "d54" distance P8 P10 = 20
  dimension "d55" distance P4 P8 = 8.6
  dimension "d57" diameter C3 = 6.5
  dimension "d61" diameter C5 = 3
  dimension "d62" distance P15 P16 = 29.3
  dimension "d63" radius A3 = 2
  dimension "d65" radius A4 = 2
  dimension "d66" radius A5 = 2
  dimension "d67" distance P29 P30 = 99.3
  dimension "d68" angle L11 L12 = 100
  dimension "d69" angle L15 L16 = 100
  dimension "d116" diameter C2 = 2.7
extrude "Extrude4" sketch "Sketch5" profile of A1 A2 C1 C2 C3 C4 L9 L10 L11 L12 L13 L14 L15 L16 A8 L17 A7 L18 L20 blind 4 from offset -32
extrude "Extrude6" sketch "Sketch5" profile of C1 C2 C3 C4 A8 L17 A7 L18 L20 blind 3
extrude "Extrude8" sketch "Sketch5" profile of C1 C2 C3 C4 L10 L14 A8 L17 A7 L18 L20 blind -1.6
sketch "Sketch6" plane through (0, 49, 0) normal (0, 1, 0) x axis (-1, 0, 0)
  line L1 (9, -27.75) -> (-9, -27.75)
  line L2 (-9, -21.25) -> (9, -21.25)
  line L3 (-40.5, -15) -> (18.5, -15)
  line L4 (-43.5, 12) -> (-43.5, -12)
  line L5 (18.5, 15) -> (-40.5, 15)
  line L6 (21.5, -12) -> (21.5, 12)
  line L7 (-43.5, 0) -> (21.5, 0)
  line L8 (-11, 15) -> (-11, -15)
  line L9 (21.25, -27.75) -> (21.25, -11.5)
  line L10 (9, -27.75) -> (21.25, -27.75)
  line L11 (14.75, -21.25) -> (9, -21.25)
  line L12 (14.75, -11.5) -> (14.75, -21.25)
  line L13 (-36.75, -21.25) -> (-9, -21.25)
  line L14 (-36.75, -11.5) -> (-36.75, -21.25)
  line L15 (-43.25, -27.75) -> (-9, -27.75)
  line L16 (-43.25, -11.5) -> (-43.25, -27.75)
  line L17 (0, -27.75) -> (0, -21.25)
  line L18 (0, -24.5) -> (12.25, -24.5)
  line L19 (-12.25, -24.5) -> (0, -24.5)
  arc A1 centre (9, -24.5) radius 3.25 clockwise from (9, -21.25) to (9, -27.75)
  arc A2 centre (-9, -24.5) radius 3.25 clockwise from (-9, -27.75) to (-9, -21.25)
  circle C1 centre (18, -11.5) radius 1.25
  arc A3 centre (18.5, -12) radius 3 clockwise from (21.5, -12) to (18.5, -15)
  arc A4 centre (18.5, 12) radius 3 clockwise from (18.5, 15) to (21.5, 12)
  arc A5 centre (-40.5, 12) radius 3 clockwise from (-43.5, 12) to (-40.5, 15)
  arc A6 centre (-40.5, -12) radius 3 clockwise from (-40.5, -15) to (-43.5, -12)
  circle C2 centre (18, 11.5) radius 1.25
  circle C3 centre (-40, -11.5) radius 1.25
  circle C4 centre (-40, 11.5) radius 1.25
  circle C5 centre (18, -11.5) radius 3.25
  circle C6 centre (-40, -11.5) radius 3.25
  circle C7 centre (18, -11.5) radius 1.075
  circle C8 centre (-40, -11.5) radius 1.075
  circle C9 centre (9, -24.5) radius 1.4
  circle C10 centre (-9, -24.5) radius 1.4
  point P13 (-43.5, 0)
  point P15 (-11, 15)
  point P12 (21.5, 0)
  point P14 (-11, -15)
  point P31 (21.25, -11.5)
  point P3 (9, -27.75)
  point P33 (9, -27.75)
  point P4 (9, -21.25)
  point P34 (9, -21.25)
  point P36 (14.75, -11.5)
  point P6 (-9, -21.25)
  point P37 (-9, -21.25)
  point P39 (-36.75, -11.5)
  point P2 (-9, -27.75)
  point P40 (-9, -27.75)
  point P42 (-43.25, -11.5)
  point P45 (9, -24.5)
  point P46 (-9, -24.5)
  point P47 (0, -21.25)
  point P48 (0, -27.75)
  point P49 (12.25, -24.5)
  point P50 (0, -24.5)
  point P51 (-12.25, -24.5)
  point P5 (9, -24.5)
  point P7 (-9, -24.5)
  point P25 (-11, 0)
  point P1 (0, 0)
  point P8 (18, -11.5)
  point P43 (18, -11.5)
  horizontal L3
  vertical L4
  horizontal L5
  vertical L6
  tangent L3 A3
  tangent L6 A3
  coincident L4 P13
  perpendicular L4 L7
  coincident L5 P15
  perpendicular L5 L8
  coincident L6 P12
  tangent L5 A4
  tangent L6 A4
  tangent L4 A5
  tangent L5 A5
  equal A4 A5
  coincident L3 P14
  tangent L3 A6
  tangent L4 A6
  equal A4 A6
  symmetric C1 L7 C2
  symmetric C1 L8 C3
  symmetric L8 C2 C4
  concentric C1 C5
  concentric C3 C6
  equal C5 C6
  coincident C5 P31
  coincident P3 P33
  coincident P4 P34
  coincident C5 P36
  tangent C5 L12
  tangent C5 L9
  parallel L9 L12
  tangent A1 L11
  tangent A1 L10
  coincident P6 P37
  tangent A2 L13
  coincident C6 P39
  coincident P2 P40
  tangent A2 L15
  coincident C6 P42
  tangent C6 L16
  parallel L14 L16
  tangent C6 L14
  concentric C1 C7
  concentric C3 C8
  equal C7 C8
  horizontal P45 P46
  equal C9 C10
  midpoint L2 P47
  midpoint L1 P48
  midpoint A1 P49
  midpoint L17 P50
  midpoint A2 P51
  coincident P5 P45
  coincident P7 P46
  midpoint L5 P15
  midpoint L8 P25
  midpoint L7 P25
  horizontal P1 P25
  perpendicular L9 L10
  perpendicular L15 L16
  dimension "d84" radius A3 = 3
  dimension "d85" diameter C1 = 2.5
  dimension "d86" distance L6 P8 = 3.5
  dimension "d87" distance L3 P8 = 3.5
  dimension "d88" distance P12 P13 = 65
  dimension "d89" distance P14 P15 = 30
  dimension "d90" radius A4 = 3
  dimension "d91" diameter C5 = 6.5
  dimension "d101" diameter C7 = 2.15
  dimension "d107" diameter C9 = 2.8
  dimension "d153" distance P43 L17 = 18
  dimension "d156" distance L3 P47 = 6.25
extrude "Extrude7" sketch "Sketch6" profile of A1 A2 C5 C6 L9 L10 L11 L12 L13 L14 L15 L16 C7 C8 blind 3 from offset 10
extrude "Extrude9" add sketch "Sketch6" profile of C5 C6 C7 C8 along normal blind 3
chamfer "Chamfer1" distance 2 distance 5 distance 8 distance 10 distance 5
fillet "Fillet1" radius 4
chamfer "Chamfer2" distance 1
extrude "Extrude10" cut sketch "Sketch6" profile of C9 C10 against normal blind 4
extrude "Extrude11" cut sketch "Sketch1" profile of A1 C1 A2 C7 L37 along normal blind 8
sketch "Sketch7" plane through (0, 0, -27.75) normal (0, 0, -1) x axis (-1, 0, 0)
  line L1 (-9, 38) -> (-9, 44)
  curve K1 (-9, 38) -> (-13.1231, 36)
  line L2 (-58.6876, 33) -> (-58.6876, 35)
  curve K2 (-22.8744, 33) -> (-21.8452, 32)
  line L3 (-9, 11) -> (-9, 22)
  curve K3 (-9, 11) -> (-14, 8.2866)
  line L4 (-14, 0) -> (-14, 8.2866)
  line L5 (14, 0) -> (-14, 0)
  line L6 (14, 8.2866) -> (14, 0)
  curve K4 (14, 8.2866) -> (9, 11)
  line L7 (9, 24) -> (9, 11)
  curve K5 (9, 24) -> (19.7703, 32)
  line L8 (27.8876, 35) -> (27.8876, 33)
  curve K6 (14.3385, 35) -> (13.1231, 36)
  line L9 (9, 44) -> (9, 38)
  line L10 (4, 44) -> (-4, 44)
  line L11 (7, 7) -> (7, 41)
  line L12 (-4, 4) -> (4, 4)
  line L13 (-7, 41) -> (-7, 7)
  line L14 (0, 48) -> (0, 0)
  line L15 (-7, 24) -> (0, 4)
  line L16 (0, 38) -> (-7, 24)
  line L17 (-6.1213, 43.1213) -> (0, 38)
  line L18 (-7, 20.9729) -> (-1.0595, 4)
  line L19 (-5.9164, 23.9311) -> (0, 7.0271)
  line L20 (0, 35.7639) -> (-5.9164, 23.9311)
  line L21 (-5.2738, 43.7161) -> (0, 39.3038)
  line L22 (-1.2479, 37.7402) -> (-6.7021, 42.3034)
  line L23 (-7, 26.2361) -> (-1.2479, 37.7402)
  line L24 (5.9164, 23.9311) -> (0, 7.0271)
  line L25 (7, 20.9729) -> (1.0595, 4)
  line L26 (0, 35.7639) -> (5.9164, 23.9311)
  line L27 (7, 26.2361) -> (1.2479, 37.7402)
  line L28 (1.2479, 37.7402) -> (6.7021, 42.3034)
  line L29 (5.2738, 43.7161) -> (0, 39.3038)
  line L30 (5.5905, 23) -> (-5.5905, 23)
  line L31 (-5.382, 25) -> (5.382, 25)
  line L32 (7, 24) -> (-7, 24)
  line L33 (-14.3385, 47) -> (-38.25, 47)
  curve K7 (-14.3385, 47) -> (-13.1231, 46)
  curve K8 (-13.1231, 46) -> (-9, 44)
  curve K9 (-13.1231, 36) -> (-14.3385, 35)
  line L34 (-58.6876, 35) -> (-14.3385, 35)
  line L35 (-22.8744, 33) -> (-58.6876, 33)
  curve K10 (19.7703, 32) -> (20.811, 33)
  line L36 (27.8876, 33) -> (20.811, 33)
  line L37 (14.3385, 35) -> (27.8876, 35)
  curve K11 (9, 44) -> (13.1231, 46)
  curve K12 (13.1231, 46) -> (14.3385, 47)
  line L38 (16.25, 47) -> (14.3385, 47)
  line L39 (16.25, 48) -> (16.25, 47)
  line L40 (-38.25, 48) -> (16.25, 48)
  line L41 (-38.25, 47) -> (-38.25, 48)
  curve K13 (-21.8452, 32) -> (-9, 22)
  curve K14 (13.1231, 36) -> (9, 38)
  arc A1 centre (-4, 7) radius 3 clockwise from (-4, 4) to (-7, 7)
  arc A2 centre (4, 7) radius 3 clockwise from (7, 7) to (4, 4)
  arc A3 centre (-4, 41) radius 3 clockwise from (-7, 41) to (-4, 44)
  arc A4 centre (4, 41) radius 3 clockwise from (4, 44) to (7, 41)
  point P1 (0, 0)
  point P21 (0, 0)
  point P35 (0, 4)
  point P36 (-7, 24)
  point P37 (0, 38)
  point P38 (-6.1213, 43.1213)
  point P2 (-9, 38)
  point P39 (-1.0595, 4)
  point P40 (-7, 20.9729)
  point P41 (0, 7.0271)
  point P43 (0, 35.7639)
  point P44 (0, 39.3038)
  point P45 (-5.2738, 43.7161)
  point P46 (-6.7021, 42.3034)
  point P48 (-7, 26.2361)
  point P51 (1.0595, 4)
  point P52 (7, 20.9729)
  point P49 (0, 7.0271)
  point P42 (-5.9164, 23.9311)
  point P50 (5.9164, 23.9311)
  point P53 (0, 35.7639)
  point P57 (0, 39.3038)
  point P58 (5.2738, 43.7161)
  point P56 (6.7021, 42.3034)
  point P47 (-1.2479, 37.7402)
  point P54 (1.2479, 37.7402)
  point P55 (7, 26.2361)
  point P59 (-5.5905, 23)
  point P60 (5.5905, 23)
  point P61 (5.382, 25)
  point P63 (7, 24)
  point P62 (-5.382, 25)
  point P22 (0, 48)
  horizontal L10
  vertical L11
  horizontal L12
  vertical L13
  coincident P1 P21
  tangent L12 A1
  tangent L13 A1
  tangent L11 A2
  tangent L12 A2
  equal A1 A2
  tangent L10 A3
  tangent L13 A3
  equal A1 A3
  tangent L10 A4
  tangent L11 A4
  equal A1 A4
  midpoint L12 P35
  midpoint L13 P36
  coincident L14 P37
  midpoint A3 P38
  horizontal P2 P37
  coincident L12 P39
  coincident L13 P40
  parallel L15 L18
  coincident L14 P41
  coincident L14 P43
  parallel L16 L20
  coincident L14 P44
  coincident A3 P45
  parallel L17 L21
  coincident A3 P46
  coincident L13 P48
  parallel L20 L23
  parallel L17 L22
  parallel L15 L19
  symmetric L14 P39 P51
  symmetric L14 P40 P52
  symmetric L14 P41 P49
  symmetric L14 P42 P50
  symmetric L14 P43 P53
  symmetric L14 P44 P57
  symmetric L14 P45 P58
  symmetric L14 P46 P56
  symmetric L14 P47 P54
  symmetric L14 P48 P55
  coincident L19 P59
  coincident L24 P60
  horizontal L30
  coincident L26 P61
  parallel L30 L31
  midpoint L11 P63
  coincident L20 P62
  coincident P22 L40
  perpendicular L14 L40
  dimension "d117" distance P1 L12 = 4
  dimension "d119" distance L9 L11 = 2
  dimension "d120" radius A1 = 3
  dimension "d121" distance L1 L13 = 2
  dimension "d122" distance L15 L18 = 1
  dimension "d123" distance L15 L19 = 1
  dimension "d124" distance L16 L20 = 1
  dimension "d125" distance L16 L23 = 1
  dimension "d126" distance L17 L22 = 1
  dimension "d127" distance L17 L21 = 1
  dimension "d131" distance L30 L32 = 1
  dimension "d132" distance L31 L32 = 1
  dimension "d152" distance L10 P22 = 4
extrude "Extrude12" cut sketch "Sketch7" profile of L10 L11 L12 L13 A1 A2 A3 A4 L18 L19 L20 L21 L22 L23 L24 L25 L26 L27 L28 L29 L30 L31 to an object
chamfer "Chamfer3" sketch "Sketch5" distance 0.5
chamfer "Chamfer4" distance 1.3
mirror "Mirror1" mirrorStitchTolerance 0.1
sketch "Sketch8" plane through (0, 0, -27.75) normal (0, 0, -1) x axis (-1, 0, 0)
  line L1 (-4, 3.5) -> (-0.3547, 3.5)
  line L2 (-7.5, 23.915) -> (-7.5, 7)
  line L3 (-0.3547, 3.5) -> (-7.5, 23.915)
  line L4 (6.8287, 43.0612) -> (0.624, 37.8701)
  line L5 (7.5, 24.118) -> (7.5, 41)
  line L6 (0.624, 37.8701) -> (7.5, 24.118)
  line L7 (-6.128, 43.7788) -> (0, 38.6519)
  line L8 (4, 44.5) -> (-4, 44.5)
  line L9 (0, 38.6519) -> (6.128, 43.7788)
  line L10 (-9, 38) -> (-9, 44)
  curve K1 (-9, 38) -> (-13.1231, 36)
  line L11 (-58.6876, 33) -> (-58.6876, 35)
  curve K2 (-22.8744, 33) -> (-21.8452, 32)
  line L12 (-9, 11) -> (-9, 22)
  curve K3 (-9, 11) -> (-14, 8.2866)
  line L13 (-14, 0) -> (-14, 8.2866)
  line L14 (14, 0) -> (-14, 0)
  line L15 (14, 8.2866) -> (14, 0)
  curve K4 (14, 8.2866) -> (9, 11)
  line L16 (9, 24) -> (9, 11)
  curve K5 (9, 24) -> (19.7703, 32)
  line L17 (27.8876, 35) -> (27.8876, 33)
  curve K6 (14.3385, 35) -> (13.1231, 36)
  line L18 (9, 44) -> (9, 38)
  line L19 (-7.5, 41) -> (-7.5, 24.118)
  line L20 (-0.624, 37.8701) -> (-6.8287, 43.0612)
  line L21 (-7.5, 24.118) -> (-0.624, 37.8701)
  line L22 (6.191, 24.5) -> (0, 36.882)
  line L23 (-6.191, 24.5) -> (6.191, 24.5)
  line L24 (0, 36.882) -> (-6.191, 24.5)
  line L25 (0, 5.5135) -> (6.2953, 23.5)
  line L26 (-6.2953, 23.5) -> (0, 5.5135)
  line L27 (6.2953, 23.5) -> (-6.2953, 23.5)
  line L28 (7.5, 7) -> (7.5, 23.915)
  line L29 (0.3547, 3.5) -> (4, 3.5)
  line L30 (7.5, 23.915) -> (0.3547, 3.5)
  curve K7
  curve K8
  curve K9
  curve K10
  line L31 (-14.3385, 47) -> (-38.25, 47)
  curve K11 (-14.3385, 47) -> (-13.1231, 46)
  curve K12 (-13.1231, 46) -> (-9, 44)
  curve K13 (-13.1231, 36) -> (-14.3385, 35)
  line L32 (-58.6876, 35) -> (-14.3385, 35)
  line L33 (-22.8744, 33) -> (-58.6876, 33)
  curve K14 (19.7703, 32) -> (20.811, 33)
  line L34 (27.8876, 33) -> (20.811, 33)
  line L35 (14.3385, 35) -> (27.8876, 35)
  curve K15 (9, 44) -> (13.1231, 46)
  curve K16 (13.1231, 46) -> (14.3385, 47)
  line L36 (16.25, 47) -> (14.3385, 47)
  line L37 (16.25, 48) -> (16.25, 47)
  line L38 (-38.25, 48) -> (16.25, 48)
  line L39 (-38.25, 47) -> (-38.25, 48)
  curve K17 (-21.8452, 32) -> (-9, 22)
  curve K18 (13.1231, 36) -> (9, 38)
  arc A1 centre (-4, 7) radius 3.5 clockwise from (-4, 3.5) to (-7.5, 7)
  arc A2 centre (4, 41) radius 3.5 clockwise from (6.8287, 43.0612) to (7.5, 41)
  arc A3 centre (-4, 41) radius 3.5 clockwise from (-6.128, 43.7788) to (-4, 44.5)
  arc A4 centre (4, 41) radius 3.5 clockwise from (4, 44.5) to (6.128, 43.7788)
  arc A5 centre (-4, 41) radius 3.5 clockwise from (-7.5, 41) to (-6.8287, 43.0612)
  arc A6 centre (4, 7) radius 3.5 clockwise from (7.5, 7) to (4, 3.5)
  point P1 (0, 0)
  horizontal K9
  dimension "d135" distance P1 = 27
  dimension "d138" distance K8 K10 = 5
  dimension "d160" distance P1 K8 = 10
  dimension "d134" Text2-Height = 5
  dimension "d136" distance = 6
extrude "Extrude13" cut sketch "Sketch8" against normal blind 1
